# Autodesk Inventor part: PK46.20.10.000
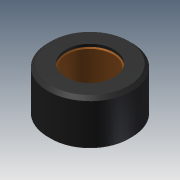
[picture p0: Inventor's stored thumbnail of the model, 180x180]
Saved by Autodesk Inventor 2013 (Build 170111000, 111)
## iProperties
Created: 2012-02
Part Number: PK46.20.10.000
Material: Silicone
Document SubType Name: Modeling
Designer: tedescj
Density: 1.25 g/cm^3
Author: tedescj
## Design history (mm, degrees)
sketch "Sketch1"
  geometry: C1 r 15 at (-176.079, -140) reference; C2 r 20 at (-176.079, -140); C3 r 11 at (-176.079, -140); C4 r 11.5 at (-176.079, -140)
  constraints: 4 centre point, 2 coincident, 1 concentric, 2 other
  dimensions: "d0" = 40 diameter of C2; "d22" = 22 diameter of C3; "d23" = 0.5 radial gap between concentric circles of C4 C3
extrude "Extrusion1" new body sketch "Sketch1" distance "d1" = 22; taper "d2" = 0 deg
workplane "Work Plane1"
sketch "Sketch2"
  geometry: C1 r 13 at (0, 0); C2 r 11 at (0, 0) reference
  constraints: 1 centre point
  dimensions: "d24" = 2 radial gap between concentric circles of C1 C2
extrude "Extrusion2" new body sketch "Sketch2" stored distance "d9" = 19.5 (computed from d1); taper "d10" = 0 deg
chamfer "Chamfer1" distance "d16" = 1.5; stored, may be unused: second distance "d17" = 2, angle "d18" = 45 deg
chamfer "Chamfer2" distance "d19" = 0.5; stored, may be unused: second distance "d20" = 2, angle "d21" = 45 deg
node "PK46.20.11.000"
node "PK46.20.12.000"
